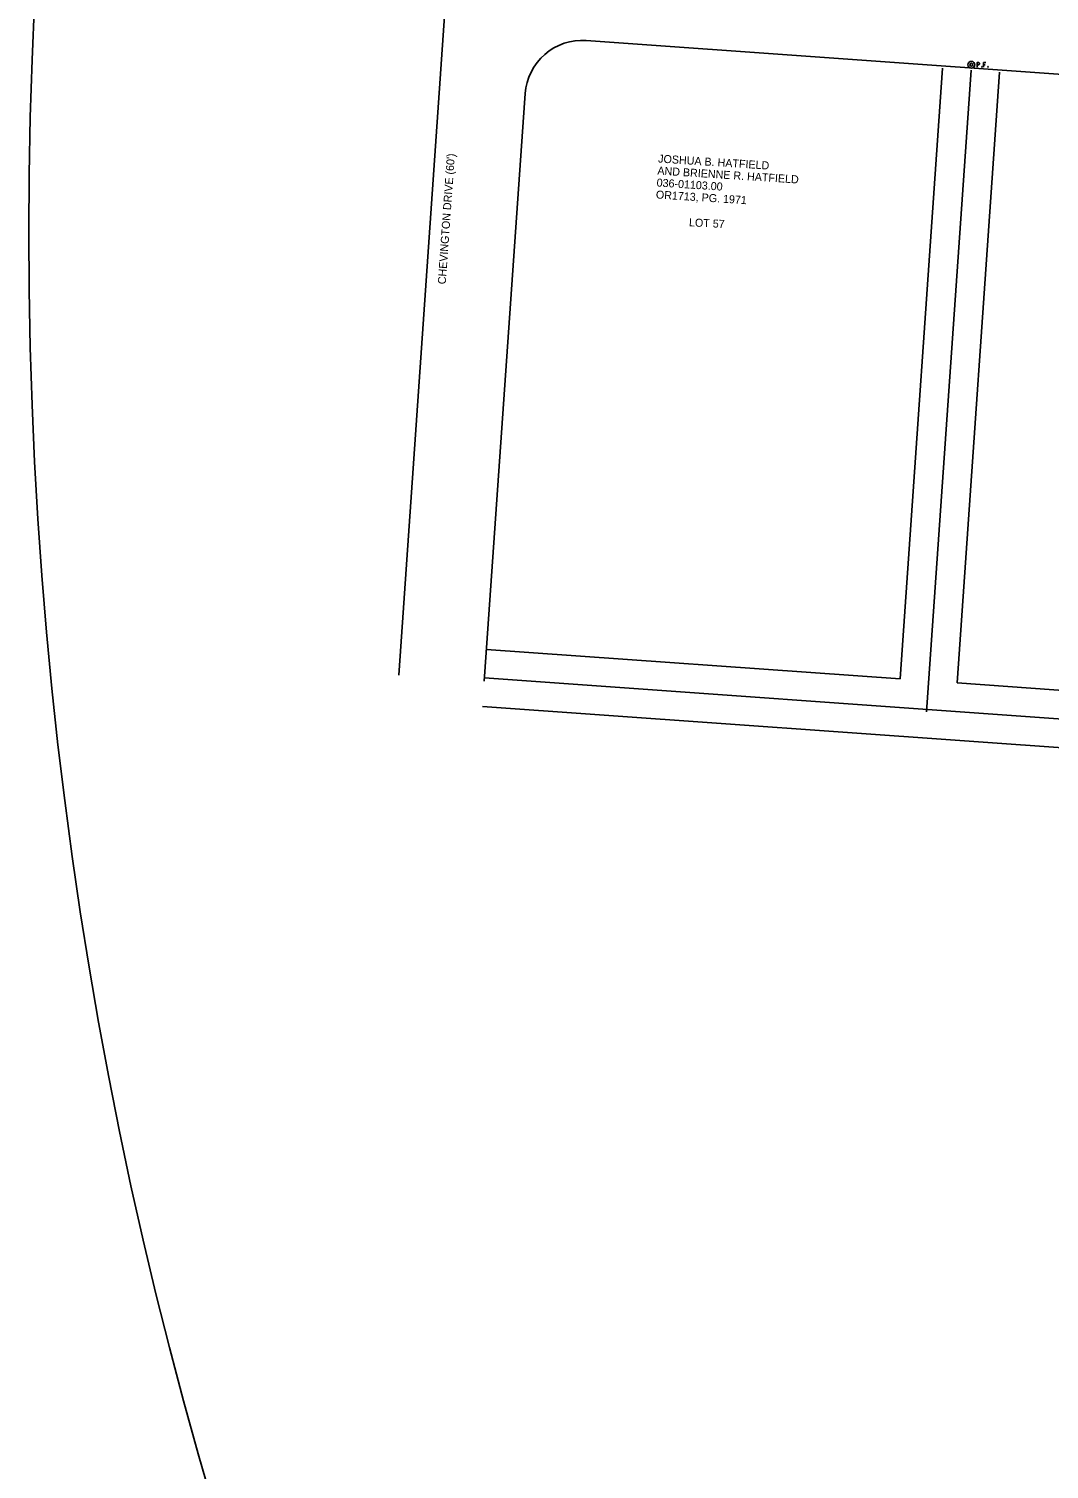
# Model space of a CAD drawing. Extents: x 1898254 to 1901377, y 701554 to 704886.
# Drawn here: x 1898254 to 1898611, y 702797 to 703301 of the extents above; entities that cross this region are included whole.
import ezdxf

# ---------------------------------------------------------------- set-up
doc = ezdxf.new("R2010")
doc.units = 0
for name, color, linetype in [('DV_X_Property_Line', 7, 'Continuous'), ('DV_X_Text', 7, 'Continuous'), ('RW_X_CL', 7, 'Continuous'), ('RW_X_Esmt_General', 7, 'Continuous'), ('RW_X_Fee_RW', 7, 'Continuous'), ('RW_X_Text', 7, 'Continuous'), ('SC_Scratch2', 7, 'Continuous'), ('SV_X_Mon_Cells_Found', 7, 'Continuous')]:
    doc.layers.add(name, color=color, linetype=linetype)

msp = doc.modelspace()

# ---------------------------------------------------------------- linework, layer by layer
at = {"layer": 'DV_X_Property_Line'}
for p, q in [((1898568.34, 703062.05), (1898583.97, 703286.5)), ((1899469, 702998.85), (1898413.79, 703073.89))]:
    msp.add_line(p, q, dxfattribs=at)
at = {"layer": 'RW_X_CL'}
msp.add_line((1898383.79, 703074.9), (1898401.58, 703330.4), dxfattribs=at)
at = {"layer": 'RW_X_Esmt_General'}
for p, q in [((1898559.12, 703073.58), (1898574, 703287.2)), ((1898579.07, 703072.16), (1898593.95, 703285.81)), ((1898559.12, 703073.58), (1898414.48, 703083.87)), ((1898693.78, 703064.01), (1898579.07, 703072.16)), ((1899458.32, 702989.59), (1898413.09, 703063.91))]:
    msp.add_line(p, q, dxfattribs=at)
at = {"layer": 'RW_X_Fee_RW'}
for p, q in [((1899763.77, 703203.46), (1898449.4, 703296.93)), ((1898413.71, 703072.82), (1898428.03, 703278.37))]:
    msp.add_line(p, q, dxfattribs=at)
msp.add_arc((1898447.98, 703276.98), 20, 85.9325, 176.0159, dxfattribs=at)
at = {"layer": 'SC_Scratch2'}
msp.add_circle((1899815.76, 703229.84), 1561.35, dxfattribs=at)
at = {"layer": 'SV_X_Mon_Cells_Found'}
for points in [[(1898586.06, 703287.63), (1898586.06, 703289.23), (1898586.59, 703289.23), (1898586.65, 703289.21), (1898586.72, 703289.19), (1898586.76, 703289.16), (1898586.79, 703289.14), (1898586.83, 703289.07), (1898586.87, 703289.01), (1898586.89, 703288.91), (1898586.89, 703288.76), (1898586.88, 703288.71), (1898586.85, 703288.63), (1898586.81, 703288.55), (1898586.77, 703288.51), (1898586.73, 703288.48), (1898586.68, 703288.46), (1898586.59, 703288.44), (1898586.06, 703288.44)], [(1898587.7, 703287.84), (1898587.76, 703287.84), (1898587.79, 703287.81), (1898587.82, 703287.76), (1898587.82, 703287.7), (1898587.79, 703287.65), (1898587.76, 703287.63), (1898587.7, 703287.63), (1898587.67, 703287.65), (1898587.64, 703287.7), (1898587.64, 703287.76), (1898587.67, 703287.81), (1898587.7, 703287.84)], [(1898589.07, 703289.23), (1898588.31, 703289.23), (1898588.31, 703287.63)], [(1898588.31, 703288.44), (1898588.85, 703288.44)], [(1898589.85, 703287.84), (1898589.91, 703287.84), (1898589.94, 703287.81), (1898589.97, 703287.76), (1898589.97, 703287.7), (1898589.94, 703287.65), (1898589.91, 703287.63), (1898589.85, 703287.63), (1898589.82, 703287.65), (1898589.79, 703287.7), (1898589.79, 703287.76), (1898589.82, 703287.81), (1898589.85, 703287.84)]]:
    msp.add_lwpolyline(points, dxfattribs=at)
for radius in [1.2, 0.495]:
    msp.add_circle((1898584.06, 703288.43), radius, dxfattribs=at)

# ---------------------------------------------------------------- texts
at = {"layer": 'DV_X_Text'}
for s, rotation, p in [('AND BRIENNE R. HATFIELD', 356.3351, (1898474.19, 703250.06)), ('JOSHUA B. HATFIELD', 356.3351, (1898474.46, 703254.26)), ('036-01103.00', 356.3351, (1898473.92, 703245.87)), ('OR1713, PG. 1971', 356.3351, (1898473.66, 703241.68)), ('LOT 57', 357.0949, (1898485.25, 703231.95))]:
    msp.add_text(s, height=2.8, rotation=rotation, dxfattribs=at).set_placement(p)
at = {"layer": 'RW_X_Text'}
msp.add_text("CHEVINGTON DRIVE (60')", height=2.8, rotation=85.9325, dxfattribs=at).set_placement((1898400.21, 703211.57))

doc.saveas('drawing.dxf')
